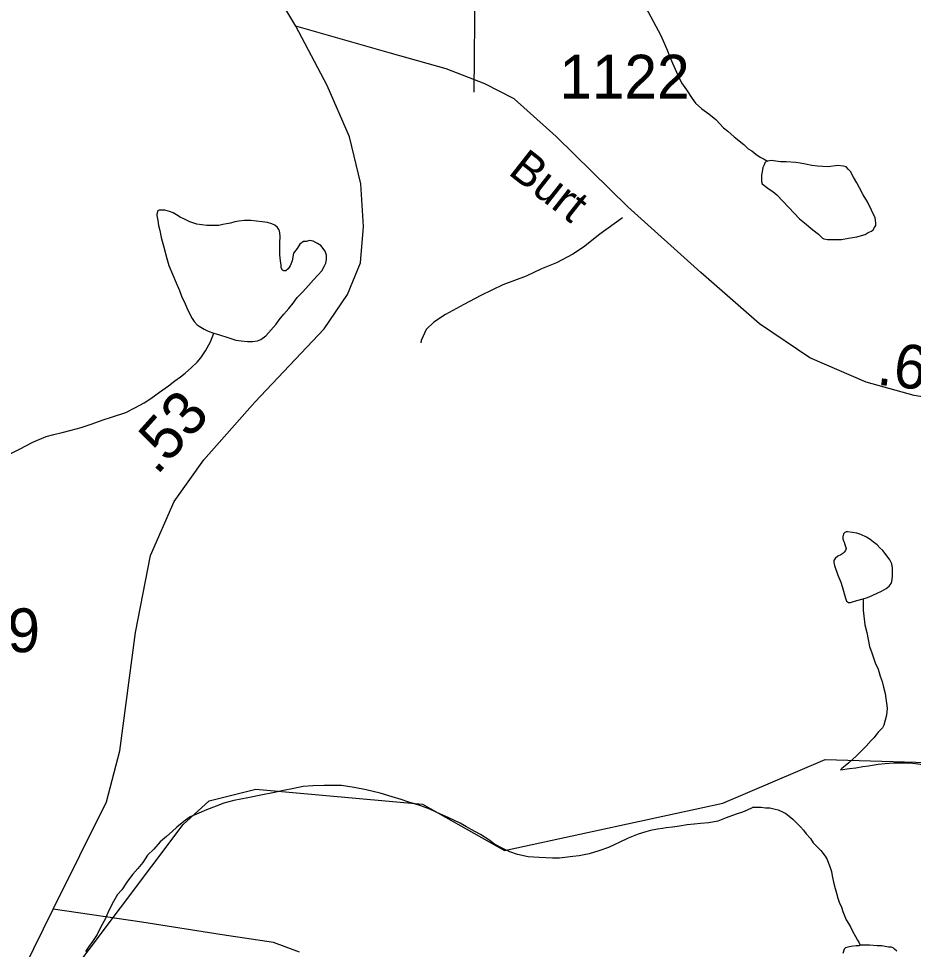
# Model space of a CAD drawing. Extents: x 2001466 to 2224147, y 644118 to 847247.
# Drawn here: x 2039151 to 2041705, y 663505 to 666162 of the extents above; entities that cross this region are included whole.
import ezdxf

# ---------------------------------------------------------------- set-up
doc = ezdxf.new("R2010")
doc.units = 0
for name, color, linetype in [('Exist Hydrographic Misc Water Feature', 7, 'Continuous'), ('Exist Road Non-System Type 51', 7, 'Continuous'), ('Exist Road Secondary Mileage Hundredths English Label', 7, 'Continuous'), ('Exist Road Secondary Type 51 Attributed', 7, 'Continuous'), ('Exist Road Secondary Type 51 Label', 7, 'Continuous'), ('Exist Road Secondary Type 51 Number Label', 7, 'Continuous')]:
    doc.layers.add(name, color=color, linetype=linetype)

msp = doc.modelspace()

# ---------------------------------------------------------------- linework, layer by layer
at = {"layer": 'Exist Hydrographic Misc Water Feature'}
for points in [[(2040942.4, 666191.5), (2040982.6, 666115.6), (2040994.7, 666089.6), (2041002.7, 666069.7), (2041010.7, 666049.7), (2041021, 666025.7), (2041032.9, 665999.8), (2041042.9, 665977.8), (2041057.1, 665957.8), (2041073.1, 665933.9), (2041083.1, 665919.9), (2041100.9, 665903.9), (2041121, 665890), (2041141.1, 665874), (2041163.1, 665850), (2041175.2, 665840.1), (2041193.2, 665824.1), (2041221.3, 665802.2), (2041233.2, 665790.2), (2041243.3, 665784.2), (2041255.3, 665774.2), (2041267.2, 665766.2), (2041279.3, 665760.3), (2041286.3, 665756), (2041289.2, 665754.3)], [(2041289.2, 665754.3), (2041286.3, 665756), (2041281.2, 665750.3), (2041279.3, 665744.3), (2041275.4, 665736.3), (2041273.4, 665724.2), (2041271.3, 665714.3), (2041271.3, 665706.3), (2041271.3, 665696.3), (2041273.4, 665690.3), (2041285.3, 665680.3), (2041293.3, 665674.3), (2041303.5, 665668.4), (2041315.4, 665658.4), (2041349.5, 665622.4), (2041379.6, 665590.5), (2041393.6, 665578.5), (2041417.5, 665558.6), (2041433.5, 665546.6), (2041445.6, 665534.6), (2041449.5, 665532.6), (2041459.6, 665530.7), (2041473.5, 665530.7), (2041499.6, 665530.7), (2041519.7, 665534.7), (2041531.6, 665536.8), (2041543.7, 665538.8), (2041567.6, 665544.9), (2041575.6, 665550.9), (2041585.7, 665554.9), (2041589.6, 665558.9), (2041593.7, 665564.9), (2041597.6, 665570.9), (2041597.6, 665578.9), (2041595.5, 665592.9), (2041585.5, 665614.9), (2041573.6, 665638.8), (2041561.3, 665658.8), (2041551.4, 665678.8), (2041543.4, 665692.8), (2041533.4, 665708.7), (2041525.2, 665724.8), (2041519.3, 665730.8), (2041513.3, 665738.8), (2041505.3, 665740.7), (2041489.3, 665742.7), (2041461.2, 665738.6), (2041431.3, 665740.5), (2041415.3, 665742.5), (2041397.2, 665746.5), (2041381.3, 665748.5), (2041369.4, 665750.4), (2041341.3, 665752.3), (2041325.3, 665752.3), (2041299.2, 665756.3), (2041289.2, 665754.3)], [(2039708.4, 665263.4), (2039724.4, 665259.4), (2039748.4, 665251.5), (2039770.6, 665243.5), (2039786.6, 665241.6), (2039804.6, 665239.6), (2039818.5, 665239.7), (2039832.5, 665241.7), (2039842.5, 665245.7), (2039856.5, 665255.7), (2039886.4, 665289.7), (2039894.4, 665301.7), (2039908.4, 665317.8), (2039922.3, 665333.8), (2039934.2, 665349.8), (2039946.3, 665365.8), (2039962.3, 665381.9), (2039978.1, 665399.9), (2039992.2, 665415.9), (2040006.2, 665429.9), (2040016.2, 665441.9), (2040024, 665455.9), (2040028.1, 665463.9), (2040030, 665473.9), (2040030, 665486), (2040026.1, 665498), (2040014, 665514), (2040003.9, 665519.9), (2039991.8, 665525.9), (2039982, 665527.9), (2039971.9, 665525.8), (2039963.9, 665525.8), (2039954.1, 665517.8), (2039946.1, 665505.8), (2039936, 665491.8), (2039931.9, 665469.8), (2039926.2, 665455.8), (2039920.1, 665447.8), (2039914.1, 665441.7), (2039908.2, 665441.7), (2039904.1, 665443.7), (2039900.2, 665449.8), (2039900.2, 665457.8), (2039898.1, 665469.7), (2039896.1, 665487.7), (2039896.1, 665501.7), (2039896.1, 665519.7), (2039897.9, 665541.7), (2039895.9, 665555.7), (2039893.8, 665559.7), (2039889.9, 665565.7), (2039881.9, 665571.7), (2039873.9, 665575.6), (2039861.8, 665579.6), (2039845.8, 665581.6), (2039829.8, 665583.6), (2039813.8, 665585.6), (2039796, 665585.5), (2039779.8, 665583.5), (2039767.9, 665581.4), (2039755.8, 665577.4), (2039743.9, 665575.4), (2039733.9, 665573.4), (2039722, 665571.4), (2039706, 665571.3), (2039687.9, 665571.3), (2039674, 665573.3), (2039659.8, 665575.3), (2039639.9, 665581.3), (2039632, 665585.2), (2039624, 665589.2), (2039611.9, 665595.2), (2039601.8, 665601.1), (2039592, 665607.1), (2039581.9, 665611.1), (2039568, 665615.1), (2039560, 665615.1), (2039552, 665615.1), (2039547.9, 665613.1), (2039545.8, 665603.1), (2039545.8, 665599.1), (2039547.9, 665585.1), (2039549.9, 665571.1), (2039554, 665557.1), (2039557.9, 665537.1), (2039565.9, 665509.1), (2039574.1, 665477.1), (2039580.1, 665457.1), (2039600.2, 665407.2), (2039610.2, 665385.2), (2039616.2, 665369.2), (2039626.4, 665347.3), (2039634.4, 665329.3), (2039646.3, 665305.3), (2039652.5, 665297.3), (2039660.5, 665287.3), (2039666.6, 665283.3), (2039680.5, 665275.4), (2039692.4, 665269.4), (2039708.4, 665263.4)], [(2039121.2, 664916.4), (2039153.2, 664932.4), (2039191.1, 664952.5), (2039229.2, 664968.6), (2039251.2, 664974.6), (2039275.2, 664980.6), (2039301, 664986.7), (2039329.1, 664994.7), (2039361.1, 665004.8), (2039389, 665014.9), (2039418.9, 665024.9), (2039456.8, 665037), (2039482.9, 665051), (2039508.9, 665065.1), (2039528.8, 665077.1), (2039552.8, 665095.1), (2039578.8, 665113.2), (2039596.7, 665127.2), (2039612.7, 665139.2), (2039626.8, 665149.2), (2039644.7, 665165.3), (2039660.7, 665181.3), (2039670.7, 665193.3), (2039684.7, 665213.4), (2039698.6, 665239.4), (2039708.4, 665263.4)], [(2041561.5, 664505), (2041573.4, 664509.1), (2041587.5, 664515.1), (2041601.5, 664521.1), (2041613.4, 664527.1), (2041627.5, 664535.1), (2041635.5, 664541.1), (2041641.5, 664549.2), (2041643.5, 664555.2), (2041645.4, 664569.2), (2041645.4, 664581.2), (2041645.4, 664593.2), (2041643.3, 664605.2), (2041637.4, 664617.1), (2041627.3, 664631.1), (2041617.3, 664643.1), (2041609.3, 664651.1), (2041601.3, 664659.1), (2041591.2, 664667), (2041581.2, 664675), (2041571.1, 664681), (2041555.1, 664689), (2041543.2, 664692.9), (2041531.1, 664694.9), (2041517.2, 664696.9), (2041513.3, 664696.9), (2041509.2, 664694.9), (2041505.3, 664690.8), (2041503.3, 664682.8), (2041503.3, 664676.8), (2041505.3, 664670.8), (2041507.2, 664666.8), (2041509.2, 664660.8), (2041511.3, 664654.8), (2041513.3, 664648.9), (2041511.3, 664642.9), (2041507.4, 664638.9), (2041503.3, 664634.9), (2041497.3, 664630.9), (2041489.3, 664626.9), (2041481.3, 664620.9), (2041477.4, 664614.9), (2041477.4, 664608.9), (2041479.3, 664600.9), (2041489.5, 664572.9), (2041497.5, 664552.8), (2041501.4, 664540.9), (2041507.6, 664520.9), (2041511.5, 664506.9), (2041513.5, 664498.9), (2041519.7, 664494.9), (2041525.6, 664494.9), (2041543.7, 664501), (2041561.5, 664505)], [(2041561.5, 664505), (2041561.5, 664493), (2041561.5, 664473), (2041565.8, 664431), (2041571.7, 664409), (2041575.6, 664389.1), (2041579.7, 664369.1), (2041585.9, 664351.1), (2041595.9, 664323.1), (2041603.9, 664305.1), (2041609.9, 664285.1), (2041616, 664269.2), (2041619.9, 664253.2), (2041624, 664235.2), (2041626.1, 664221.2), (2041628.1, 664207.2), (2041630.2, 664193.2), (2041628.1, 664173.2), (2041624, 664159.2), (2041620.1, 664145.2), (2041616.2, 664137.2), (2041604.1, 664125.2), (2041598.2, 664117.2), (2041592.3, 664109.1), (2041584.3, 664101.1), (2041570.3, 664085.1), (2041558.4, 664073.1), (2041550.4, 664065.1), (2041542.4, 664057.1), (2041520.3, 664037), (2041510.4, 664029), (2041500.4, 664021), (2041496.5, 664017)], [(2039146.4, 663342.5), (2039263.3, 663386), (2039620.3, 663861.1), (2039695.3, 663928.5), (2039828.4, 663961.9), (2040303.3, 663919.5), (2040537.3, 663786.7), (2041161.2, 663921.7), (2041453.4, 664047), (2041744.4, 664037.8), (2042328.4, 663898), (2042636.4, 663983.7), (2043053.2, 663942.3), (2043311.4, 663825.5), (2043420.3, 663751.1), (2043545.4, 663709.3), (2043894.4, 663751.3)], [(2041496.5, 664017), (2041522.5, 664021), (2041540.4, 664023), (2041560.5, 664027.1), (2041576.3, 664029.1), (2041604.3, 664033.2), (2041624.2, 664035.2), (2041650.3, 664037.2), (2041678.4, 664037.3), (2041694.4, 664037.4), (2041710.4, 664035.4), (2041724.3, 664033.4), (2041738.2, 664031.4), (2041752.4, 664029.4), (2041764.3, 664027.5), (2041780.3, 664025.5), (2041790.3, 664021.5), (2041796.3, 664019.5), (2041802.4, 664013.5), (2041808.4, 664011.5), (2041816.4, 664007.6), (2041826.4, 664003.6), (2041832.4, 664001.6), (2041840.4, 663999.6)], [(2041248.8, 663910.6), (2041244.7, 663908.6), (2041230.7, 663902.5), (2041216.8, 663896.5), (2041198.8, 663890.4), (2041170.7, 663880.4), (2041146.7, 663870.4), (2041120.8, 663866.3), (2041096.8, 663864.2), (2041078.8, 663862.2), (2041058.9, 663860.2), (2041036.8, 663856.2), (2041016.9, 663854.1), (2040998.8, 663852.1), (2040988.8, 663850), (2040974.8, 663848), (2040954.7, 663844), (2040940.8, 663840), (2040918.9, 663833.9), (2040890.8, 663821.8), (2040864.9, 663809.8), (2040853, 663803.8), (2040835, 663795.8), (2040806.9, 663785.7), (2040779, 663777.6), (2040750.9, 663771.6), (2040732.9, 663769.6), (2040695.1, 663765.5), (2040675.1, 663765.5), (2040637.1, 663767.4), (2040605.1, 663769.3), (2040575, 663775.3), (2040553, 663783.2), (2040533, 663793.2), (2040509, 663805.2), (2040493, 663817.2), (2040469, 663833.1), (2040442.9, 663847), (2040429, 663855), (2040410.9, 663864.9), (2040376.9, 663880.9), (2040354.8, 663890.8), (2040324.8, 663904.8), (2040298.8, 663914.8), (2040280.7, 663920.7), (2040264.7, 663924.7), (2040242.8, 663932.7), (2040216.8, 663940.6), (2040182.9, 663950.5), (2040142.7, 663960.4), (2040108.7, 663966.4), (2040072.8, 663972.3), (2040046.8, 663972.3), (2040022.8, 663972.2), (2039990.8, 663972.1), (2039962.9, 663970.1), (2039936.9, 663964.1), (2039906.9, 663958), (2039876.8, 663951.9), (2039846.8, 663945.9), (2039804.8, 663937.8), (2039764.8, 663929.7), (2039736.9, 663921.7), (2039715, 663913.6), (2039686.9, 663903.6), (2039665, 663893.6), (2039641, 663883.5), (2039627, 663873.5), (2039603, 663853.5), (2039589.1, 663841.5), (2039573.1, 663827.4), (2039555.1, 663811.4), (2039537.2, 663791.3), (2039519.2, 663773.3), (2039505.2, 663753.2), (2039491.3, 663735.2), (2039477.3, 663719.2), (2039461.3, 663699.2), (2039445.6, 663675.2), (2039433.5, 663661.2), (2039421.4, 663641.1), (2039413.4, 663625.1), (2039405.6, 663609.1), (2039397.6, 663591.1), (2039385.7, 663569), (2039375.6, 663547.1), (2039361.7, 663527.1), (2039351.6, 663513.1), (2039341.8, 663499)], [(2041248.8, 663910.6), (2041270.7, 663910.6), (2041282.6, 663908.6), (2041294.7, 663908.6), (2041302.7, 663906.6), (2041310.7, 663904.7), (2041318.7, 663902.7), (2041332.7, 663896.7), (2041340.7, 663892.7), (2041350.7, 663884.7), (2041360.7, 663876.7), (2041372.6, 663864.8), (2041382.7, 663854.8), (2041390.7, 663844.8), (2041398.9, 663834.8), (2041410.8, 663820.9), (2041418.8, 663808.9), (2041428.8, 663798.9), (2041440.9, 663786.9), (2041452.8, 663770.9), (2041459, 663760.9), (2041462.9, 663751), (2041467, 663739), (2041470.9, 663727), (2041472.9, 663715), (2041477, 663697), (2041481.1, 663679), (2041485, 663665), (2041489.1, 663651.1), (2041493, 663639.1), (2041499.2, 663625), (2041503.3, 663613), (2041507.2, 663603), (2041513.1, 663589.1), (2041519.3, 663579.1), (2041525.2, 663569.1), (2041531.4, 663557.1), (2041539.3, 663541.1), (2041545.3, 663531.2), (2041549.4, 663525.2), (2041553.3, 663517.2)], [(2041553.3, 663517.2), (2041549.4, 663515.2), (2041541.4, 663515.2), (2041527.2, 663513.1), (2041517.4, 663511.1), (2041511.3, 663509.1), (2041507.4, 663505.1), (2041503.5, 663493)], [(2041657.3, 663499.4), (2041651.3, 663505.4), (2041647.4, 663509.4), (2041641.3, 663511.4), (2041633.3, 663511.3), (2041615.2, 663515.3), (2041601.3, 663515.2), (2041579.3, 663517.2), (2041567.2, 663517.2), (2041557.4, 663517.2), (2041553.3, 663517.2)]]:
    msp.add_lwpolyline(points, dxfattribs=at)
at = {"layer": 'Exist Road Non-System Type 51'}
for points in [[(2040451.6, 665951.8), (2040454.3, 666257), (2040446.2, 666359.6), (2040443.5, 666421.8), (2040446.2, 666465), (2040448.9, 666505.5), (2040454.3, 666540.6), (2040467.7, 666564.4)], [(2040874.6, 665592.6), (2040809.6, 665545.9), (2040762.9, 665508.9), (2040732.5, 665489.5), (2040686, 665464.4), (2040643.6, 665447.3), (2040599.2, 665426.2), (2040532.7, 665401.5), (2040470.1, 665370.8), (2040421.6, 665345.8), (2040369, 665316.9), (2040336.5, 665295.5), (2040314.1, 665274), (2040299.5, 665242.3), (2040299.3, 665236.3)]]:
    msp.add_lwpolyline(points, dxfattribs=at)
at = {"layer": 'Exist Road Secondary Type 51 Attributed'}
for points in [[(2039941.9, 666139.6), (2039888.1, 666231.5), (2039829, 666337.1), (2039782.5, 666408.9), (2039719.2, 666491.3), (2039557.1, 666659.3), (2039371.4, 666881.1), (2039289.5, 666994.1), (2039248.4, 667061.7), (2039195.6, 667225.5), (2039104.8, 667545.5), (2039079.5, 667666), (2039064.7, 667794.8), (2039069.5, 668028.3), (2039054.7, 668367.4), (2039027.8, 668703.3), (2038995, 668984.3), (2038946.5, 669250.5), (2038875.7, 669736.4), (2038863.1, 669837.8), (2038867.3, 669913.8), (2038899, 670017.4), (2038968.1, 670183.9)], [(2039250, 663619.2), (2039402, 663925.5), (2039440, 664071.2), (2039484.3, 664409.3), (2039527.1, 664629), (2039594.6, 664783.2), (2039679.6, 664902.6), (2039825.3, 665066.3), (2040023.2, 665276.5), (2040089.7, 665373.7), (2040127.2, 665464.6), (2040135.6, 665568.1), (2040128.2, 665689.6), (2040095.5, 665823.7), (2040031.6, 665970.5), (2039941.9, 666139.6)], [(2042427.2, 664940.4), (2042370.9, 664957.5), (2042223.1, 665001.9), (2041979.2, 665042), (2041707.4, 665085.4), (2041570.2, 665123.4), (2041409.7, 665193.1), (2041265.6, 665290.3), (2041097.8, 665437.1), (2040889.8, 665624.1), (2040685.6, 665824.8), (2040565.3, 665932.5), (2040481.9, 665975.8), (2040371, 666018.1), (2040208.5, 666063.5), (2039941.9, 666139.6)], [(2038498.7, 662283.3), (2038551.2, 662410.7), (2038690.5, 662638.9), (2038892.1, 662976.9), (2039139.1, 663395.2), (2039250, 663619.2)], [(2039952.5, 663496.6), (2039878.6, 663524.1), (2039731.9, 663546.3), (2039502.3, 663582.2), (2039250, 663619.2)]]:
    msp.add_lwpolyline(points, dxfattribs=at)

# ---------------------------------------------------------------- texts
at = {"layer": 'Exist Road Secondary Mileage Hundredths English Label'}
for s, rotation, p in [('.62', 353.2639, (2041597.7, 665117.2)), ('.53', 48.0708, (2039545.5, 664855.7))]:
    msp.add_text(s, height=125, rotation=rotation, dxfattribs=at).set_placement(p)
at = {"layer": 'Exist Road Secondary Type 51 Label'}
msp.add_text('Burt', height=95, rotation=321.8212, dxfattribs=at).set_placement((2040545.1, 665719.7))
at = {"layer": 'Exist Road Secondary Type 51 Number Label'}
for s, p in [('1122', (2040694.4, 665933.4)), ('1119', (2038840.2, 664353.1))]:
    msp.add_text(s, height=125, dxfattribs=at).set_placement(p)

doc.saveas('drawing.dxf')
